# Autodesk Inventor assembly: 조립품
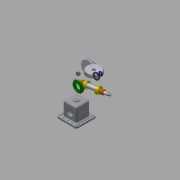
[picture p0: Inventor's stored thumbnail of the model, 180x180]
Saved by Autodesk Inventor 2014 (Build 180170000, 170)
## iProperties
Created: 2018-11
Part Number: 조립품
Document SubType Name: Assembly
Designer: kh
Author: kh
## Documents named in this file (13)
- C:\Users\kh\Desktop\481107V1020\조립품.iam
- C:\Users\kh\Desktop\481107V1020\본체.ipt
- C:\Users\kh\Desktop\481107V1020\너트 M12x1.25.ipt
- C:\Users\kh\Desktop\481107V1020\베어링 6203.ipt
- C:\Users\kh\Desktop\481107V1020\V벨트풀리.ipt
- C:\Users\kh\Desktop\481107V1020\볼트 M4.ipt
- C:\Users\kh\Desktop\481107V1020\부시.ipt
- C:\Users\kh\Desktop\481107V1020\스퍼기어.ipt
- C:\Users\kh\Desktop\481107V1020\오일 실 26 38 8.ipt
- C:\Users\kh\Desktop\481107V1020\와셔 12x24.ipt
- C:\Users\kh\Desktop\481107V1020\축.ipt
- C:\Users\kh\Desktop\481107V1020\커버.ipt
- C:\Users\kh\Desktop\481107V1020\키 5x5x12.ipt
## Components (1 placed, 1 different names)
1. V벨트풀리:1
